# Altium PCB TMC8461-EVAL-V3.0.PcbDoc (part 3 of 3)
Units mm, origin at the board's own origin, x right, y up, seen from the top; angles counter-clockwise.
Board outline 79 x 85 mm, 4 copper layers (Top Layer, Mid1, Mid2, Bottom Layer), stack 1.572 mm thick; 182 components, 192 nets, 883 pads, 381 vias.
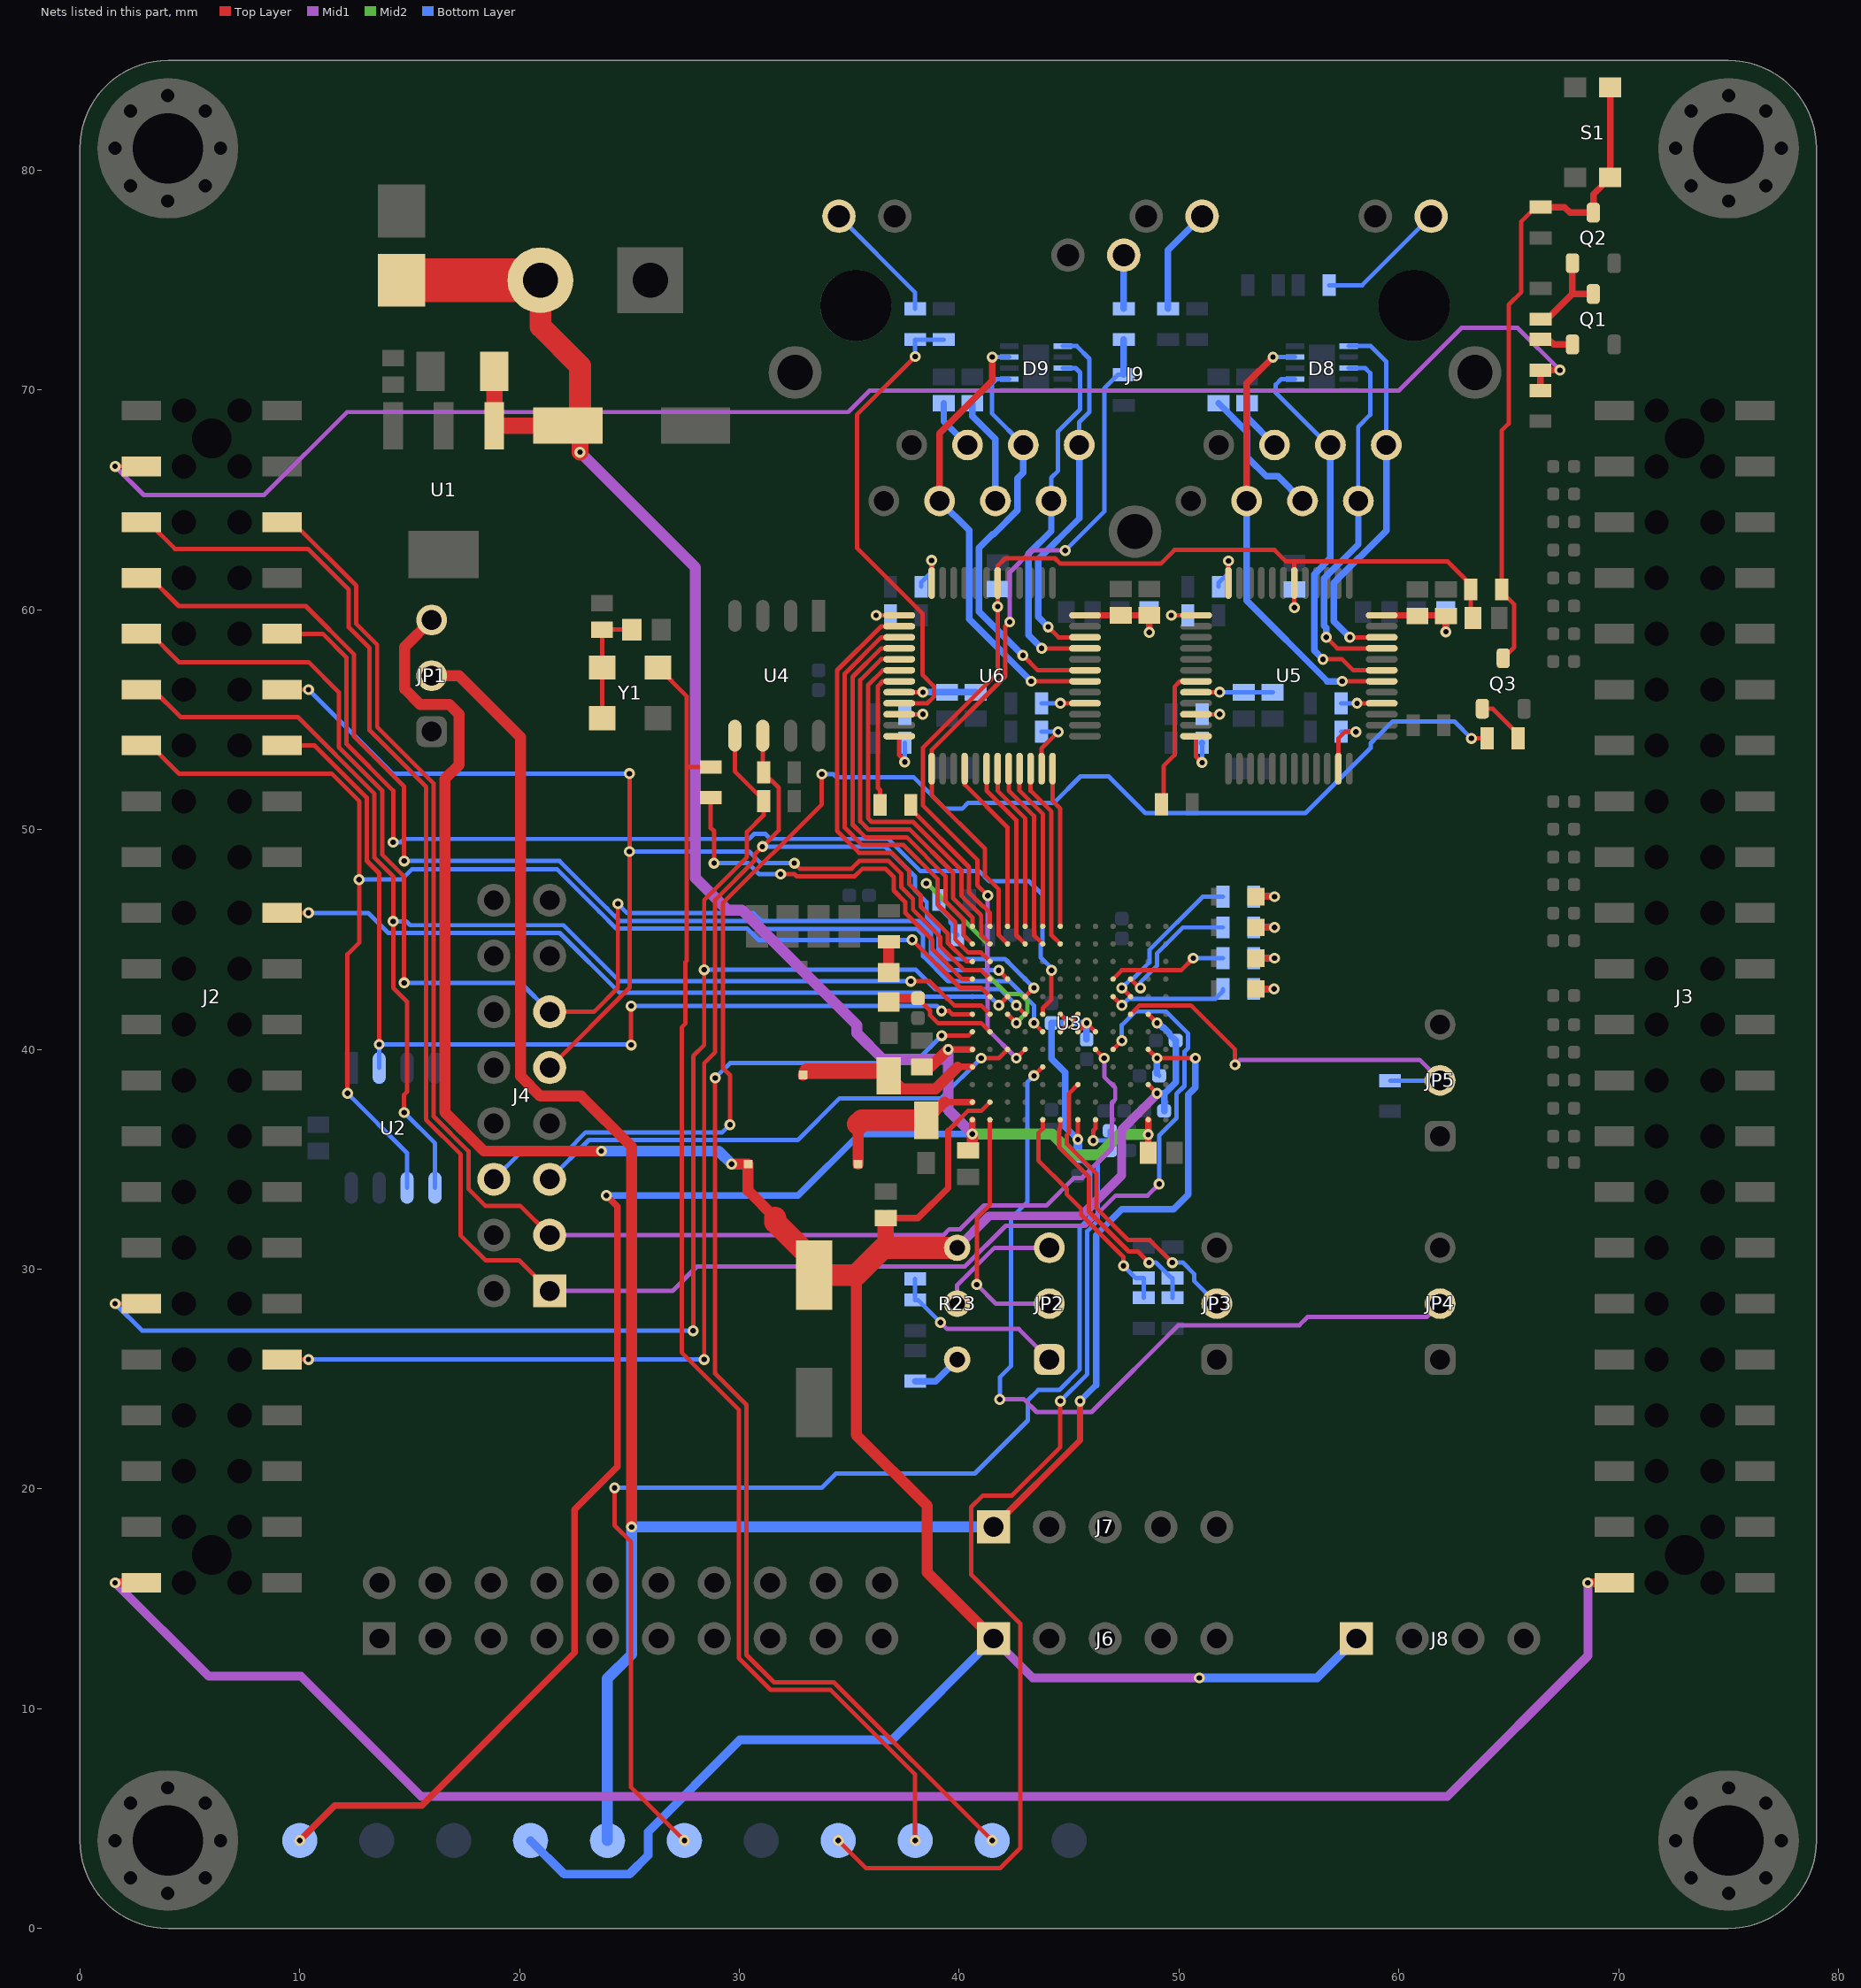
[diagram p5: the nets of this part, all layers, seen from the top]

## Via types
v1: diameter 0.5, hole 0.25, Top Layer to Bottom Layer, tented both sides, 379 vias
v2: diameter 0.5/0.5/0.5/0.5 (per signal layer), hole 0.25, Top Layer to Bottom Layer, tented both sides, 1 vias
v3: diameter 0.55, hole 0.25, Top Layer to Bottom Layer, tented both sides, 1 vias

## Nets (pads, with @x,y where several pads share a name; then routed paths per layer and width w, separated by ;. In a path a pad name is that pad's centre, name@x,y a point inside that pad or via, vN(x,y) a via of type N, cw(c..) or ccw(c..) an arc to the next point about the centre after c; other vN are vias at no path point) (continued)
MII2_LED_ACT: R63.1 R69.1 U6.9 | length 21.8
  Top Layer w0.2: U6.9@37.275,55.75 38.557,55.75 38.85,56.043 38.85,56.525 38.325,57.05 38.325,59.841 35.35,62.816 35.35,68.875 v1(38,71.525)
  Bottom Layer w0.2: v1(38,71.525) R69.1@38,72.3 R63.1@39.3,72.3
MII2_LINK: R66.2 R68.1 U3.K2 U6.13 | length 33.6
  Top Layer w0.2: U3.K2@42.2,44.8 41.8,45.2 41.8,47.275 41.175,47.9 41.175,49.125 38.75,51.55 U6.13@38.75,52.775 38.75,53.625 42.1,56.975 42.1,59.25 v1(42.3,59.45)
  Mid1 w0.2: v1(42.3,59.45) 42.3,61.7 43.3,62.7 v1(44.825,62.7)
  Bottom Layer w0.2: v1(44.825,62.7) 46.6,64.475 46.6,70.075 47.225,70.7 R66.2@47.49,70.7
  Bottom Layer w0.3: R66.2@47.49,70.7 R68.1@47.49,72.3
MII2_RX_CLK: U3.K1 U6.16 | length 8
  Top Layer w0.2: U6.16@40.25,52.775 40.25,52.05 42.2,50.1 U3.K1@42.2,45.6
MII2_RX_DV: U3.G2 U6.22 | length 8.5
  Top Layer w0.2: U6.22@43.25,52.775 43.25,51.767 44.2,50.817 44.2,45.2 U3.G2@44.6,44.8
MII2_RX_ER: U3.G1 U6.24 | length 7.3
  Top Layer w0.2: U6.24@44.25,52.775 44.25,51.305 44.6,50.955 U3.G1@44.6,45.6
MII2_RXD0: U3.H1 U6.21 | length 7.6
  Top Layer w0.2: U6.21@42.75,52.775 42.75,51.772 43.8,50.722 U3.H1@43.8,45.6
MII2_RXD1: U3.H2 U6.20 | length 8.6
  Top Layer w0.2: U6.20@42.25,52.775 42.25,51.777 43.4,50.627 43.4,45.2 U3.H2@43.8,44.8
MII2_RXD2: U3.J1 U6.19 | length 7.7
  Top Layer w0.2: U6.19@41.75,52.775 41.75,51.768 43,50.518 U3.J1@43,45.6
MII2_RXD3: U3.J2 U6.18 | length 8.7
  Top Layer w0.2: U6.18@41.25,52.775 41.25,51.773 42.6,50.423 42.6,45.2 U3.J2@43,44.8
MII2_TX_CLK: R59.1 U3.L1 | length 7.1
  Top Layer w0.2: R59.1@37.65,51.125 R59.1@37.65,51.15 ; R59.1@37.8,51.125 37.8,50.95 40.45,48.3 40.45,47.143 41.093,46.5 41.115,46.5 41.4,46.215 U3.L1@41.4,45.6
MII2_TX_EN: U3.M3 U6.2 | length 20.5
  Top Layer w0.2: U6.2@37.275,59.25 36.447,59.25 34.45,57.253 34.45,49.942 35.442,48.95 36.907,48.95 37.725,48.132 37.725,47.518 38.25,46.993 38.25,46.5 39.483,45.267 39.483,44.847 40.33,44 U3.M3@40.6,44
MII2_TXD0: U3.L2 U6.6 | length 16.9
  Top Layer w0.2: U6.6@37.275,57.25 36.53,57.25 35.85,56.57 35.85,50.521 36.021,50.35 37.905,50.35 40.1,48.155 40.1,46.998 40.948,46.15 40.95,46.15 41,46.1 41,45.2 U3.L2@41.4,44.8
MII2_TXD1: U3.M1 U6.5 | length 16.6
  Top Layer w0.2: U6.5@37.275,57.75 36.446,57.75 35.5,56.804 35.5,50.376 35.876,50 37.76,50 39.725,48.035 39.725,46.878 40.6,46.003 U3.M1@40.6,45.6
MII2_TXD2: U3.M2 U6.4 | length 18.2
  Top Layer w0.2: U6.4@37.275,58.25 36.451,58.25 35.15,56.949 35.15,50.232 35.732,49.65 37.615,49.65 39.375,47.89 39.375,46.733 40.2,45.908 40.2,45.2 U3.M2@40.6,44.8
MII2_TXD3: U3.L3 U6.3 | length 20.4
  Top Layer w0.2: U6.3@37.275,58.75 36.456,58.75 34.8,57.094 34.8,50.087 35.587,49.3 37.47,49.3 39.025,47.745 39.025,46.588 39.833,45.78 39.833,44.992 40.418,44.407 40.993,44.407 U3.L3@41.4,44
NetC13_2: C13.2 L1.2 U3.L7 | length 5.4
  Top Layer w0.2: L1.2@36.8,42.16 L1.2@36.965,42.325 ; C13.2@38.125,42.325 38.125,42.311 38.68,41.756 38.68,41.55 39.03,41.2 41,41.2 U3.L7@41.4,40.8
  Top Layer w0.4: L1.2@36.965,42.325 C13.2@38.125,42.325
NetC16_2: C16.2 C17.2 TP8.1 U3.E12 | length 47.9
  Top Layer w0.2: v1(34.5,4) 35.75,2.75 41.875,2.75 42.775,3.65 42.775,13.875 40.55,16.1 40.55,19.175 41.075,19.7 42.4,19.7 44.6,21.9 v1(44.6,24) ; v1(46.1,35.85) 46.1,36.3 46.2,36.4 U3.E12@46.2,36.8
  Bottom Layer w0.2: v1(44.6,24) 45.825,25.225 45.825,31.725 46.305,32.205 46.305,34.855 C16.2@46.85,35.4 46.85,35.85 ; v1(46.1,35.85) 46.85,35.85 ; C17.2@46.85,36.3 46.85,35.85
NetC28_2: C28.2 L4.1 Y1.1 Y1.4 | length 5.5
  Top Layer w0.2: Y1.1@23.4,55 Y1.1@23.4,55.125 ; Y1.1@23.76,55.075 Y1.4@23.76,57.375 23.76,59.09 C28.2@23.75,59.1 L4.1@25.11,59.1
NetC34_2: C34.2 C35.2 L5.2 U5.36 | length 4.6
  Top Layer w0.3: U5.36@59.225,59.75 62.125,59.75 62.14,59.735 v1(62.14,59)
  Bottom Layer w0.3: v1(62.14,59) L5.2@62.14,59.9
NetC36_2: C36.2 C37.2 U5.8 | length 3.5
  Top Layer w0.2: U5.8@50.775,56.25 v1(51.85,56.25)
  Bottom Layer w0.2: v1(51.85,56.25) C37.2@54.275,56.25
NetC38_2: C38.2 J9.A4 | length 6.3
  Bottom Layer w0.3: C38.2@51.8,69.4 53.1,68.1 53.1,66.95 53.975,66.075 54.505,66.075 J9.A4@55.62,64.96
NetC39_2: C39.2 J9.A5 | length 2.4
  Bottom Layer w0.3: C39.2@53.1,69.4 53.1,68.75 J9.A5@54.35,67.5
NetC43_2: C43.2 C44.2 L6.2 U6.36 | length 4.6
  Top Layer w0.3: U6.36@45.725,59.75 C43.2@48.65,59.75 v1(48.65,58.975)
  Bottom Layer w0.3: L6.2@48.64,59.9 48.64,58.985 v1(48.65,58.975)
NetC45_2: C45.2 C46.2 U6.8 | length 3.5
  Top Layer w0.2: U6.8@37.275,56.25 v1(38.35,56.25)
  Bottom Layer w0.3: v1(38.35,56.25) C46.2@39.45,56.25 C45.2@40.75,56.25
NetC47_2: C47.2 J9.B4 | length 4.9
  Bottom Layer w0.3: C47.2@40.6,69.4 40.6,68.825 41.65,67.775 J9.B4@41.65,64.96
NetC48_2: C48.2 J9.B5 | length 2.3
  Bottom Layer w0.3: C48.2@39.3,69.4 39.3,68.58 J9.B5@40.38,67.5
NetD2_1: D2.1 L2.1 U3.M9 | length 8.5
  Top Layer w0.3: 39.925,39.2 U3.M9@40.6,39.2
  Top Layer w0.5: L2.1@32.899,38.833 L2.1@33.065,39 ; D2.1@36.6,39 D2.1@36.8,38.8 37.4,38.2 38.925,38.2 39.925,39.2
  Top Layer w0.7: L2.1@33.065,39 D2.1@36.6,39
NetD3_1: D3.1 L3.1 U3.M11 | length 7.4
  Top Layer w0.2: D3.1@38.5,36.775 D3.1@38.575,36.85
  Top Layer w0.3: 39.325,37.6 U3.M11@40.6,37.6
  Top Layer w0.5: L3.1@35.399,34.78 35.399,36.599 ; D3.1@38.575,36.85 39.325,37.6
  Top Layer w1: 35.399,36.599 35.575,36.775 D3.1@38.5,36.775
NetD4_2: D4.2 R36.2 | length 1.8
  Top Layer w0.3: D4.2@53.5,46.95 v1(54.35,46.95)
  Bottom Layer w0.3: R36.2@53.4,46.95 v1(54.35,46.95)
NetD5_2: D5.2 R37.2 | length 1.8
  Top Layer w0.3: D5.2@53.5,45.55 v1(54.35,45.55)
  Bottom Layer w0.3: R37.2@53.4,45.55 v1(54.35,45.55)
NetD6_2: D6.2 R38.2 | length 1.8
  Top Layer w0.3: D6.2@53.5,44.15 v1(54.35,44.15)
  Bottom Layer w0.3: R38.2@53.4,44.15 v1(54.35,44.15)
NetD7_2: D7.2 R39.2 | length 1.7
  Top Layer w0.3: D7.2@53.5,42.75 v1(54.325,42.75)
  Bottom Layer w0.3: R39.2@53.4,42.75 v1(54.325,42.75)
NetJ9_A9: J9.A9 R57.2 | length 5.9
  Bottom Layer w0.2: R57.2@56.825,74.775 58.335,74.775 J9.A9@61.47,77.91
NetJ9_A11: J9.A11 R58.2 | length 4.9
  Bottom Layer w0.3: R58.2@49.5,73.7 49.5,76.36 J9.A11@51.05,77.91
NetJ9_B9: J9.B9 R68.2 | length 2.4
  Bottom Layer w0.3: R68.2@47.49,73.7 J9.B9@47.49,76.14
NetJ9_B12: J9.B12 R69.2 | length 5.6
  Bottom Layer w0.2: J9.B12@34.53,77.91 38,74.44 R69.2@38,73.7
NetJP2_1: JP2.1 R25.1 R26.2 | length 8.2
  Mid1 w0.2: v1(39.15,27.575) 39.45,27.275 42.715,27.275 JP2.1@44.1,25.89
  Bottom Layer w0.2: R25.1@38,29.55 R26.2@38,28.6 38.125,28.6 v1(39.15,27.575)
NetJP2_2: JP2.2 U3.L12 | length 11.4
  Top Layer w0.2: v1(40.8,29.3) 40.8,32.325 41.4,32.925 U3.L12@41.4,36.8
  Mid1 w0.2: v1(40.8,29.3) 41.67,28.43 JP2.2@44.1,28.43
NetJP2_3: JP2.3 R23.2 | length 5.7
  Mid1 w0.2: R23.2@39.909,28.43 39.909,29.273 41.606,30.97 JP2.3@44.1,30.97
NetJP3_2: JP3.2 U3.F10 | length 13.9
  Top Layer w0.2: U3.F10@45.4,38.4 45,38 45,36.207 44.9,36.107 44.9,35.693 46.25,34.343 46.25,32.768 47.693,31.325 48.675,31.325 v1(49.7,30.3)
  Bottom Layer w0.2: v1(49.7,30.3) 50.175,30.3 50.7,29.775 50.7,29.45 JP3.2@51.72,28.43
NetJP4_2: JP4.2 U3.H9 | length 38.2
  Top Layer w0.2: v1(43.4,38.8) U3.H9@43.8,39.2
  Mid1 w0.2: v1(41.85,24.075) 42.95,24.075 43.525,23.5 46.025,23.5 49.975,27.45 55.475,27.45 55.85,27.825 61.275,27.825 JP4.2@61.88,28.43
  Bottom Layer w0.2: v1(41.85,24.075) 41.85,25.085 42.35,25.585 42.35,32.3 43.1,33.05 43.1,38.5 v1(43.4,38.8)
NetJP5_2: JP5.2 R47.1 U3.C6 | length 18.7
  Top Layer w0.2: U3.C6@47.8,41.6 48.2,42 50.542,42 52.55,39.992 v1(52.55,39.3) ; v1@52.578,39.252 v1@52.578,39.4
  Mid1 w0.2: v1(52.55,39.3) 52.775,39.525 60.945,39.525 JP5.2@61.88,38.59
  Bottom Layer w0.2: R47.1@59.6,38.58 61.87,38.58 JP5.2@61.88,38.59
NetL1_1: L1.1 R22.2 | length 1.5
  Top Layer w0.5: L1.1@36.8,43.49 R22.2@36.8,44.9 R22.2@36.8,44.95
NetQ1_1: Q1.1 R31.1 | length 1.6
  Top Layer w0.3: R31.1@66.445,72.305 66.81,72.305 67.04,72.075 Q1.1@67.9,72.075
NetQ1_3: Q1.3 Q2.1 R32.1 | length 4.3
  Top Layer w0.3: R32.1@66.45,73.225 66.74,73.225 67.89,74.375 Q1.3@68.85,74.375 ; 67.9,74.385 Q2.1@67.9,75.775
NetQ2_3: Q2.3 Q3.3 R33.1 R34.1 S1.1 S1.2 | length 30.4
  Top Layer w0.2: Q3.3@64.75,57.8 65.25,58.3 65.25,60.25 64.675,60.825 R34.1@64.675,60.925 64.675,68.15 65,68.475 65,73.882 65.575,74.457 65.575,77.675 66.225,78.325 R33.1@66.45,78.325
  Top Layer w0.3: R33.1@66.45,78.325 67.54,78.325 67.79,78.075 Q2.3@68.85,78.075 68.85,78.91 S1.2@69.62,79.68 S1.1@69.62,83.78
NetQ3_1: Q3.1 R35.1 | length 2.6
  Top Layer w0.2: Q3.1@63.8,55.225 Q3.1@63.8,55.5 64.275,55.5 65.425,54.35 R35.1@65.425,54.15
NetR23_1: R23.1 R24.2 | length 2.3
  Bottom Layer w0.3: R24.2@38,24.9 38.919,24.9 R23.1@39.909,25.89 R23.1@39.92,25.901
NetR27_1: R27.1 TP9.1 Y1.3 | length 61.1
  Top Layer w0.2: Y1.3@26.3,57.375 27.6,56.075 27.6,52.85 ; R27.1@28.7,52.85 27.6,52.85 ; v1(38,4) 38,7.005 34.155,10.85 31.43,10.85 29.975,12.305 29.975,23.608 27.375,26.208 27.375,41 27.55,41.175 27.55,43.977 27.6,44.027 27.6,52.85
NetR27_2: R27.2 U3.M4 | length 18.2
  Top Layer w0.2: R27.2@28.7,51.45 28.7,50.075 28.85,49.925 v1(28.85,48.475) ; v1(31.875,47.975) 32.505,47.975 32.605,47.875 35.25,47.875 35.6,48.225 36.642,48.225 37.025,47.842 37.025,47.229 37.55,46.704 37.55,46.21 38.783,44.977 38.783,44.557 40.14,43.2 U3.M4@40.6,43.2
  Bottom Layer w0.2: v1(28.85,48.475) 30.4,48.475 30.9,47.975 v1(31.875,47.975)
NetR28_1: R28.1 R29.2 U3.K6 | length 12.4
  Top Layer w0.2: U3.K6@42.2,41.6 v1(42.6,41.2)
  Mid2 w0.2: v1(38.502,47.552) 38.548,47.552 41.275,44.825 41.275,43.41 42.16,42.525 42.782,42.525 43.1,42.207 43.1,41.7 v1(42.6,41.2)
  Bottom Layer w0.2: v1(38.502,47.552) 38.548,47.552 39.075,47.025 R29.2@39.075,46.8 39.075,46.475 39.6,45.95 39.6,45.775 39.725,45.65 39.725,45.4 R28.1@39.925,45.2
NetR36_1: R36.1 U3.C5 | length 7.4
  Top Layer w0.2: v1@47.5,42.7 v1(47.4,42.8) U3.C5@47.8,42.4
  Bottom Layer w0.2: v1(47.4,42.8) 47.8,43.2 47.897,43.2 48.655,43.958 48.655,44.525 51.08,46.95 R36.1@52,46.95
NetR37_1: R37.1 U3.C4 | length 6
  Top Layer w0.2: U3.C4@47.8,43.2 48.2,42.8 v1(48.25,42.8)
  Bottom Layer w0.2: v1(48.25,42.8) 48.25,43.058 49.005,43.813 49.005,44.38 50.175,45.55 R37.1@52,45.55
NetR38_1: R38.1 U3.D4 | length 5.4
  Top Layer w0.2: U3.D4@47,43.2 47.4,43.6 50.1,43.6 v1(50.65,44.15)
  Bottom Layer w0.2: v1@50.6,44.15 v1(50.65,44.15) R38.1@52,44.15
NetR39_1: R39.1 U3.D5 | length 5.5
  Top Layer w0.2: U3.D5@47,42.4 v1(47.4,42)
  Bottom Layer w0.2: v1(47.4,42) 47.7,42.3 51.65,42.3 52,42.65 R39.1@52,42.75
NetR40_1: R40.1 R42.2 U3.G12 | length 10.7
  Top Layer w0.2: U3.G12@44.6,36.8 44.6,36.4 44.55,36.35 44.55,35.548 45.9,34.198 45.9,32.62 47.712,30.808 48.127,30.808 v1(48.635,30.3)
  Bottom Layer w0.2: v1(48.635,30.3) 48.95,30.3 49.65,29.6 R40.1@49.7,29.6 R42.2@49.7,28.7
NetR41_1: R41.1 R43.2 U3.H12 | length 10.4
  Top Layer w0.2: U3.H12@43.8,36.8 43.8,36.385 43.6,36.185 43.6,34.943 44.9,33.643 44.9,33.393 45.55,32.743 45.55,32.475 47.475,30.55 v1(47.475,30.15)
  Bottom Layer w0.2: v1(47.475,30.15) 48.025,29.6 R41.1@48.4,29.6 R43.2@48.4,28.7
NetR48_2: R48.2 U5.7 | length 6.6
  Top Layer w0.2: R48.2@49.3,51.15 49.3,52.895 49.8,53.395 49.8,56.5 50.05,56.75 U5.7@50.775,56.75
NetR49_2: R49.2 U5.23 | length 3
  Top Layer w0.2: U5.23@57.25,52.775 57.25,54.15 57.55,54.45 v1(58.05,54.45)
  Bottom Layer w0.2: R49.2@57.375,54.45 v1(58.05,54.45)
NetR50_2: R50.2 U5.1 | length 1.9
  Top Layer w0.2: v1(49.65,59.75) U5.1@50.775,59.75
  Bottom Layer w0.2: v1(49.65,59.75) R50.2@50.4,59.75
NetR51_2: R51.2 U5.28 | length 1.8
  Top Layer w0.2: v1(58.1,55.75) U5.28@59.225,55.75
  Bottom Layer w0.2: R51.2@57.375,55.75 v1(58.1,55.75)
NetR53_2: R53.2 U5.10 | length 1.9
  Top Layer w0.2: U5.10@50.775,55.25 v1(51.85,55.25)
  Bottom Layer w0.2: R53.2@51.05,55.25 v1(51.85,55.25)
NetR54_2: R54.2 U5.12 | length 2.4
  Top Layer w0.2: U5.12@50.775,54.25 50.775,53.325 v1(51.05,53.05)
  Bottom Layer w0.2: v1(51.05,53.05) R54.2@51.05,53.95 R54.2@51.05,53.725
NetR56_1: R56.1 U5.48 | length 2.4
  Top Layer w0.2: U5.48@52.25,61.225 v1(52.25,62.225)
  Bottom Layer w0.2: R56.1@51.8,61.05 51.8,61.225 52.25,61.675 v1(52.25,62.225)
NetR59_2: R59.2 U6.7 | length 6.5
  Top Layer w0.2: R59.2@36.4,51.125 36.4,51.8 36.3,51.9 36.3,56.525 36.525,56.75 U6.7@37.275,56.75
NetR60_2: R60.2 U6.23 | length 2.7
  Top Layer w0.2: U6.23@43.75,52.775 43.75,53.7 v1(44.5,54.45)
  Bottom Layer w0.2: R60.2@43.75,54.45 v1(44.5,54.45)
NetR61_2: R61.2 U6.1 | length 1.7
  Top Layer w0.2: v1(36.225,59.75) U6.1@37.275,59.75
  Bottom Layer w0.2: v1(36.225,59.75) R61.2@36.875,59.75
NetR62_2: R62.2 U6.28 | length 2
  Top Layer w0.2: v1(44.6,55.75) U6.28@45.725,55.75
  Bottom Layer w0.2: R62.2@43.75,55.75 v1(44.6,55.75)
NetR64_2: R64.2 U6.10 | length 1.9
  Top Layer w0.2: U6.10@37.275,55.25 v1(38.35,55.25)
  Bottom Layer w0.2: R64.2@37.525,55.25 v1(38.35,55.25)
NetR65_2: R65.2 U6.12 | length 2.2
  Top Layer w0.2: U6.12@37.275,54.25 37.275,53.386 37.525,53.136 v1(37.525,53.075)
  Bottom Layer w0.2: v1(37.525,53.075) R65.2@37.525,53.95
NetR67_1: R67.1 U6.48 | length 2.4
  Top Layer w0.2: U6.48@38.75,61.225 v1(38.75,62.25)
  Bottom Layer w0.2: R67.1@38.275,61.05 38.275,61.25 38.75,61.725 v1(38.75,62.25)
NetTP10_1: TP10.1 U3.M7 | length 54.1
  Top Layer w0.2: v1(28.9,38.7) 28.9,25.25 30.325,23.825 30.325,12.45 31.575,11.2 34.3,11.2 v1(41.5,4) ; v1(39.202,40.623) 40.423,40.623 U3.M7@40.6,40.8
  Bottom Layer w0.2: v1(28.9,38.7) 29.575,39.375 37.954,39.375 v1(39.202,40.623)
PDI_EOF: J2.35 J4.11 U3.K4 | length 58.8
  Top Layer w0.2: J2.35@2.8,58.91 3.215,58.91 4.5,57.625 10.4,57.625 11.775,56.25 11.775,53.755 13.75,51.78 13.75,48.868 14.75,47.868 v1(14.75,43.025) ; J4.11@21.37,41.71 23.385,41.71 24.475,42.8 v1(24.475,46.625) ; v1(41.8,43.6) U3.K4@42.2,43.2
  Bottom Layer w0.2: v1(14.75,43.025) 20.055,43.025 J4.11@21.37,41.71 ; v1(24.475,46.625) 24.9,46.2 26.175,46.2 30.64,46.2 31.005,45.835 38.212,45.835 38.71,45.337 38.71,44.385 39.495,43.6 v1(41.8,43.6)
PDI_SOF: J2.34 J4.9 U3.L4 | length 52.3
  Top Layer w0.2: J2.34@9.2,56.37 v1(10.4,56.37) ; J4.9@21.37,39.17 25,42.8 v1(25,49) v1(25,52.55) ; v1(32.5,48.475) 32.75,48.225 35.105,48.225 35.455,48.575 36.787,48.575 37.375,47.987 37.375,47.374 37.9,46.849 37.9,46.355 39.133,45.122 39.133,44.702 40.235,43.6 41,43.6 U3.L4@41.4,43.2
  Bottom Layer w0.2: v1(10.4,56.37) 14.22,52.55 v1(25,52.55) ; v1(25,49) 30.45,49 30.975,48.475 v1(32.5,48.475)
PDI_SPI_IRQ: J2.26 U3.K5 | length 34.9
  Top Layer w0.2: J2.26@9.2,46.21 v1(10.4,46.21) ; v1(41.8,42) U3.K5@42.2,42.4
  Bottom Layer w0.2: v1(10.4,46.21) 13.115,46.21 14.025,45.3 21.825,45.3 24.55,42.575 38.225,42.575 38.4,42.4 41.4,42.4 v1(41.8,42)
PDI_WD_STATE: J2.37 U3.H7 | length 54.8
  Top Layer w0.2: J2.37@2.8,61.45 3.225,61.45 4.5,60.175 10.275,60.175 12.475,57.975 12.475,54.233 14.75,51.958 v1(14.75,48.575) ; v1(43.4,41.2) U3.H7@43.8,40.8
  Bottom Layer w0.2: v1(14.75,48.575) 21.82,48.575 23.975,46.42 23.975,46.418 24.543,45.85 29.125,45.85 30.495,45.85 30.86,45.485 38.067,45.485 38.36,45.192 38.36,44.24 39.5,43.1 42.3,43.1 43.4,42 v1(43.4,41.2)
PDI_WD_TRIGGER: J2.36 U3.H6 | length 49.3
  Top Layer w0.2: J2.36@9.2,58.91 11.045,58.91 12.125,57.83 12.125,53.9 14.25,51.775 v1(14.25,49.425) ; U3.H6@43.8,41.6 43.8,41.875 43.95,42.025 43.955,42.025 44.2,42.27 v1(44.2,43.6)
  Bottom Layer w0.2: v1(14.25,49.425) 14.6,49.425 14.75,49.575 30.44,49.575 30.665,49.8 31.185,49.8 31.41,49.575 36.775,49.575 38.225,48.125 40.9,48.125 41.375,47.65 43.175,47.65 43.79,47.035 43.79,44.879 43.7,44.789 43.7,44.193 44.2,43.693 v1(44.2,43.6)
PROM_CLK: J2.10 R45.1 U3.J5 U4.6 | length 66.2
  Top Layer w0.2: J2.10@9.2,25.89 v1(10.4,25.89) ; v1(28.4,25.89) 28.4,39.375 28.9,39.875 28.9,46.8 30.7,48.6 30.7,48.875 v1(31.05,49.225) 31.8,49.975 31.8,51.9 R45.1@31.1,52.6 31.065,52.635 U4.6@31.065,54.275 ; U3.J5@43,42.4 v1(43.4,42.8)
  Bottom Layer w0.2: v1(10.4,25.89) v1(28.4,25.89) ; v1(31.05,49.225) 36.63,49.225 38,47.855 38,47.225 38.525,46.7 38.525,46.017 39.06,45.482 39.06,44.53 39.477,44.113 42.088,44.113 v1(43.4,42.8)
PROM_DATA: J2.11 R46.1 U3.J6 U4.5 | length 72.4
  Top Layer w0.2: v1(1.6,28.43) J2.11@2.8,28.43 ; v1(27.9,27.2) 27.9,39.7 28.4,40.2 v1(28.4,43.625) 28.4,46.795 30.35,48.745 30.35,49.9 31.1,50.65 R46.1@31.1,51.3 31.1,51.35 29.795,52.655 U4.5@29.795,54.275 ; v1(42.6,42) U3.J6@43,41.6
  Bottom Layer w0.2: v1(1.6,28.43) 2.83,27.2 v1(27.9,27.2) ; v1@28.35,43.625 v1(28.4,43.625) 38.025,43.625 38.9,42.75 41.85,42.75 v1(42.6,42)
R\E\S\E\T\: C29.2 C33.2 C42.2 R34.2 U3.J8 U5.42 U6.42 | length 54.1
  Top Layer w0.2: v1(41.3,47) 40.825,47.475 40.825,48.625 38.35,51.1 38.35,52.009 38.35,53.725 41.75,57.125 v1(41.75,60.15) U6.42@41.75,61.225 41.75,62 42.1,62.35 44.35,62.35 44.6,62.1 49.168,62.1 49.793,62.725 54.35,62.725 54.875,62.2 55.25,62.2 ; v1(42.6,39.6) U3.J8@43,40 ; v1(55.25,60.1) U5.42@55.25,61.225 55.25,62.2 ; C29.2@63.375,59.625 63.275,59.725 63.275,61.15 62.225,62.2 55.25,62.2
  Mid1 w0.2: v1(41.3,47) 41.3,40.9 v1(42.6,39.6)
  Bottom Layer w0.2: v1(41.75,60.15) C42.2@41.75,60.95 ; v1(55.25,60.1) C33.2@55.25,60.925
R\S\T\_\E\X\T\: J2.41 R30.2 R31.2 | length 73.2
  Top Layer w0.2: v1(1.6,66.53) J2.41@2.8,66.53
  Top Layer w0.3: R30.2@66.445,69.98 R31.2@66.445,70.905 v1(67.325,70.905)
  Mid1 w0.2: v1(1.6,66.53) 2.905,65.225 8.375,65.225 12.15,69 34.95,69 35.925,69.975 60,69.975 62.85,72.825 65.405,72.825 v1(67.325,70.905)
RD_A_N: D8.9 J9.A6 U5.30 | length 20.3
  Top Layer w0.2: v1(57.425,56.75) U5.30@59.225,56.75
  Top Layer w0.3: J9.A6@53.08,64.96 53.08,70.305 v1(54.275,71.5)
  Bottom Layer w0.2: J9.A6@53.08,64.96 J9.A6@53.154,64.96 ; v1(54.275,71.5) D8.9@55.28,71.5
  Bottom Layer w0.3: J9.A6@53.08,64.96 53.08,60.42 56.75,56.75 v1(57.425,56.75)
RD_A_P: D8.7 J9.A3 U5.31 | length 18
  Top Layer w0.2: v1(56.55,57.75) 57.425,57.75 57.925,57.25 U5.31@59.225,57.25
  Bottom Layer w0.2: D8.7@55.28,70.5 54.65,70.5 54.4,70.25 54.4,69.875 56.775,67.5 J9.A3@56.89,67.5
  Bottom Layer w0.3: v1@56.6,57.7 v1(56.55,57.75) 56.15,58.15 56.15,61.6 56.15,61.611 56.89,62.351 J9.A3@56.89,67.5
RD_B_N: D9.9 J9.B6 U6.30 | length 20.7
  Top Layer w0.2: v1(43.275,56.75) U6.30@45.725,56.75
  Top Layer w0.3: J9.B6@39.11,64.96 39.11,68.035 41.5,70.425 v1(41.5,71.5)
  Bottom Layer w0.2: v1(41.5,71.5) D9.9@42.28,71.5
  Bottom Layer w0.3: J9.B6@39.11,64.96 40.45,63.62 40.45,59.575 v1(43.275,56.75)
RD_B_P: D9.7 J9.B3 U6.31 | length 18.6
  Top Layer w0.2: v1(42.9,57.925) 43.575,57.25 U6.31@45.725,57.25
  Bottom Layer w0.2: D9.7@42.28,70.5 41.7,70.5 41.5,70.3 41.5,68.92 J9.B3@42.92,67.5
  Bottom Layer w0.3: v1(42.9,57.925) 40.9,59.925 40.9,62.828 41.522,63.45 41.575,63.45 42.65,64.525 42.65,65.98 42.92,66.25 J9.B3@42.92,67.5
RESET_OUT: J4.5 U3.K8 | length 23.3
  Top Layer w0.2: v1(41,39.6) 41.8,39.6 U3.K8@42.2,40
  Bottom Layer w0.2: J4.5@21.37,34.09 23.155,35.875 32.665,35.875 34.565,37.775 39.175,37.775 v1(41,39.6)
RST_IN: J4.6 R35.2 | length 64.1
  Top Layer w0.2: v1(29.575,36.575) 29.575,38.825 29.25,39.15 29.25,46.65 33.75,51.15 v1(33.75,52.525) ; v1(63.3,54.15) R35.2@64.025,54.15
  Bottom Layer w0.2: J4.6@18.83,34.09 20.09,35.35 22.135,35.35 23.01,36.225 29.225,36.225 v1(29.575,36.575) ; v1(33.75,52.525) 34.275,52.525 34.425,52.375 37.94,52.375 39.365,50.95 40.132,50.95 40.407,51.225 44.318,51.225 45.518,52.425 46.8,52.425 48.475,50.75 55.755,50.75 58.725,53.72 58.725,53.932 59.018,54.225 59.025,54.225 59.725,54.925 62.525,54.925 v1(63.3,54.15)
SPI1_SCK: J2.31 U2.6 U3.L5 | length 61.2
  Top Layer w0.2: J2.31@2.8,53.83 3.22,53.83 4.5,52.55 11.455,52.55 12.7,51.305 v1(12.7,47.725) 12.7,44.85 12.175,44.325 v1(12.175,38) ; v1(37.86,44.985) 40.045,42.8 41,42.8 U3.L5@41.4,42.4
  Bottom Layer w0.2: v1(12.175,38) 14.885,35.29 U2.6@14.885,33.7 ; v1@12.65,47.725 v1(12.7,47.725) 14.638,47.725 15.113,48.2 21.7,48.2 23.625,46.275 23.625,46.273 24.398,45.5 30.35,45.5 30.865,44.985 v1(37.86,44.985)
SPI1_SDI: J2.32 U2.2 U3.M6 | length 46.3
  Top Layer w0.2: J2.32@9.2,53.83 10.67,53.83 13.05,51.45 13.05,48.578 13.615,48.013 v1(13.615,40.225) ; v1@25.075,40.225 v1(25.075,41.975) ; v1(39.2,41.75) 39.533,41.75 39.683,41.6 U3.M6@40.6,41.6
  Bottom Layer w0.2: U2.2@13.615,39.15 v1(13.615,40.225) v1@25.075,40.225 ; v1(25.075,41.975) 38.975,41.975 v1(39.2,41.75)
  other v1: 25.075,40.2
SPI1_SDO: J2.33 U2.5 U3.L6 | length 60.6
  Top Layer w0.2: J2.33@2.8,56.37 3.33,56.37 4.575,55.125 9.91,55.125 13.4,51.635 13.4,48.723 14.25,47.873 v1(14.25,45.825) 14.25,42.8 14.875,42.175 14.875,38.063 14.75,37.938 v1(14.75,37.125) ; v1(37.8,43.1) 38.655,43.1 39.449,42.307 39.471,42.307 39.778,42 41,42 U3.L6@41.4,41.6
  Bottom Layer w0.2: v1(14.25,45.825) 14.85,45.825 15.025,45.65 22,45.65 24.55,43.1 v1(37.8,43.1) ; v1(14.75,37.125) 16.155,35.72 U2.5@16.155,33.7
SYNC_OUT0: J2.39 J4.1 U3.D8 | length 89.4
  Top Layer w0.2: J2.39@2.8,63.99 3.11,63.99 4.325,62.775 10.375,62.775 12.225,60.925 12.225,59.215 13.175,58.265 13.175,54.523 15.75,51.948 15.75,36.798 17.325,35.223 17.325,31.525 18.45,30.4 19.98,30.4 J4.1@21.37,29.01 ; U3.D8@47,40 v1(47.4,40.4)
  Mid1 w0.2: J4.1@21.37,29.01 26.96,29.01 28.07,30.12 40.261,30.12 42.116,31.975 45.75,31.975 47.125,33.35 48.575,33.35 v1(49.1,33.875)
  Bottom Layer w0.2: v1(47.4,40.4) 47.4,41.107 48.018,41.725 49.411,41.725 50.415,40.721 50.415,40.065 50.25,39.9 50.25,38.334 49.89,37.975 49.89,36.879 49.1,36.089 v1(49.1,33.875)
SYNC_OUT1: J2.40 J4.3 U3.E8 | length 70.9
  Top Layer w0.2: J2.40@9.2,63.99 9.685,63.99 12.575,61.1 12.575,59.36 13.525,58.41 13.525,54.668 16.1,52.093 16.1,36.943 17.675,35.368 17.675,33.65 18.45,32.875 20.045,32.875 J4.3@21.37,31.55 ; U3.E8@46.2,40 v1(46.6,39.6)
  Mid1 w0.2: J4.3@21.37,31.55 39.287,31.55 39.557,31.82 40.045,31.82 41.125,32.9 43.975,32.9 45.225,34.15 45.602,34.15 46.95,35.498 46.95,37.575 47.1,37.725 47.1,38.25 46.6,38.75 v1(46.6,39.6)
TD_A_N: D8.3 J9.A2 U5.33 | length 16.7
  Top Layer w0.2: v1(56.7,58.75) 57.2,58.25 U5.33@59.225,58.25
  Bottom Layer w0.2: D8.3@57.72,71 58.475,71 58.7,70.775 58.7,68.875 58.15,68.325 58.15,64.97 J9.A2@58.16,64.96
  Bottom Layer w0.3: v1(56.7,58.75) 56.7,59.175 56.6,59.275 56.6,61.425 58.16,62.985 J9.A2@58.16,64.96
TD_A_P: D8.1 J9.A1 U5.34 | length 17.3
  Top Layer w0.2: v1(57.775,58.75) U5.34@59.225,58.75
  Bottom Layer w0.2: D8.1@57.72,72 58.725,72 59.43,71.295 J9.A1@59.43,67.5
  Bottom Layer w0.3: v1(57.775,58.75) 57.05,59.475 57.05,61.225 59.43,63.605 J9.A1@59.43,67.5
TD_B_N: D9.3 J9.B2 U6.33 | length 16.6
  Top Layer w0.2: v1(43.75,58.25) U6.33@45.725,58.25
  Bottom Layer w0.2: J9.B2@44.19,64.96 44.19,66.015 44.5,66.325 44.5,68.125 45.5,69.125 45.5,70.8 45.3,71 D9.3@44.72,71
  Bottom Layer w0.3: v1(43.75,58.25) 43.15,58.85 43.15,62.55 44.19,63.59 J9.B2@44.19,64.96
TD_B_P: D9.1 J9.B1 U6.34 | length 16.7
  Top Layer w0.2: v1(44.05,59.222) 44.522,58.75 U6.34@45.725,58.75
  Bottom Layer w0.2: D9.1@44.72,72 45.35,72 45.925,71.425 45.925,69 45.46,68.535 J9.B1@45.46,67.5
  Bottom Layer w0.3: v1(44.05,59.222) 43.6,59.672 43.6,62.3 45.46,64.16 J9.B1@45.46,67.5
VDD1V8: C18.2 C22.2 C23.2 TP6.1 U3.E7 U3.F6 U3.F7 U3.F12 U3.G6 U3.G7 | length 64
  Top Layer w0.2: v1(24.325,20.05) 24.325,18.338 25.075,17.588 25.075,6.425 v1(27.5,4) ; U3.G7@44.6,40.8 v1(45,41.2) ; U3.G6@44.6,41.6 v1(45,41.2) ; v1(45.4,35.9) U3.F12@45.4,36.8 ; U3.F7@45.4,40.8 v1(45.8,41.2) U3.E7@46.2,40.8 ; U3.F6@45.4,41.6 v1(45,41.2)
  Bottom Layer w0.2: v1@24.375,20.05 33.742,20.05 34.392,20.7 40.707,20.7 43.125,23.118 43.125,24.032 43.593,24.5 44.55,24.5 45.475,25.425 45.475,31.875 45.955,32.355 45.955,34.595 C18.2@45.4,35.15
  Bottom Layer w0.3: v1(45.4,35.9) 44.825,36.475 44.825,38.953 44.428,39.35 44.425,39.35 44.2,39.575 C23.2@44.2,41.2 v1(45,41.2) v1(45.8,41.2) C22.2@45.8,40.45
  Bottom Layer w0.4: C18.2@45.4,35.15 v1(45.4,35.9)
VIO2: C21.2 J7.1 JP1.2 TP5.1 U3.B8 | length 105.2
  Top Layer w0.2: U3.B8@48.6,40 v1(49,39.6) v1(50.75,39.6)
  Top Layer w0.3: J7.1@41.56,18.27 45.5,22.21 v1(45.5,24)
  Top Layer w0.5: JP1.2@16,57 17.25,57 20.05,54.2 20.05,38.775 20.95,37.875 22.8,37.875 25.1,35.575 v1(25.1,18.27)
  Bottom Layer w0.2: C21.2@49,38.9 C21.2@49.1,38.8
  Bottom Layer w0.3: v1(45.5,24) 46.225,24.725 46.225,31.55 47.4,32.725 49.75,32.725 50.425,33.4 50.425,37.944 50.75,38.269 v1(50.75,39.6) ; C21.2@49,38.9 v1(49,39.6)
  Bottom Layer w0.5: TP5.1@24,4 24,11.375 25.1,12.475 v1(25.1,18.27) J7.1@41.56,18.27
VM: J2.1 J3.1 | length 79.4
  Top Layer w0.4: v1(1.6,15.73) J2.1@2.8,15.73 ; v1(68.6,15.73) J3.1@69.8,15.73
  Mid1 w0.4: v1(1.6,15.73) 5.855,11.475 10.059,11.475 15.534,6 62.2,6 68.6,12.4 v1(68.6,15.73)
VOUT: C14.2 C15.1 C19.2 C20.2 J6.1 J8.1 JP1.3 L3.2 R23.3 R25.2 TP4.1 U3.B6 U3.B10 U3.L11 | length 148
  Top Layer w0.2: 39.5,36.3 40.4,37.2 41,37.2 U3.L11@41.4,37.6 ; U3.B10@48.6,38.4 v1(49,38) ; U3.B6@48.6,41.6 v1(49,41.2)
  Top Layer w0.3: C14.2@36.658,32.326 38.126,32.326 39.5,33.7 39.5,36.3
  Top Layer w0.5: JP1.3@16,59.54 14.775,58.315 14.775,56.4 15.475,55.7 16.8,55.7 17.25,55.25 17.25,52.95 16.6,52.3 16.6,37.15 18.375,35.375 v1(23.725,35.375) ; v1(29.65,34.78) L3.2@30.399,34.78 30.399,33.572 31.629,32.342 ; 35.316,29.73 35.316,22.459 38.55,19.225 38.55,16.2 J6.1@41.56,13.19
  Top Layer w0.75: 36.658,30.995 C14.2@36.658,32.326
  Top Layer w1: 31.629,32.342 31.629,32.138 33.407,30.36 C15.1@33.407,29.73 35.316,29.73 36.556,30.97 36.683,30.97 ; 36.658,30.995 36.683,30.97 ; R23.3@39.909,30.97 36.683,30.97
  Mid1 w0.4: R23.3@39.909,30.97 41.364,32.425 45.55,32.425 47.4,34.275 47.4,36.351 49,37.951 v1(49,38) ; J6.1@41.56,13.19 43.35,11.4 v1(50.925,11.4)
  Bottom Layer w0.2: v1(49,41.2) v1@49.05,41.2 ; 49.325,38 49.35,38
  Bottom Layer w0.3: R25.2@38,30.95 R23.3@39.889,30.95 ; v1(49,38) 49.325,38 C19.2@49.325,37.2 ; v1@49.05,41.2 49.245,41.005 49.302,41.005 49.565,40.742 49.565,40.685 C20.2@49.85,40.4 49.85,38.5 49.35,38
  Bottom Layer w0.4: TP4.1@20.5,4 22.025,2.475 25,2.475 25.85,3.325 25.85,4.4 30.025,8.575 36.945,8.575 J6.1@41.56,13.19 ; v1(50.925,11.4) 56.28,11.4 J8.1@58.07,13.19
  Bottom Layer w0.5: v1(23.725,35.375) 29.055,35.375 v1(29.65,34.78) ; R23.3@39.889,30.95 R23.3@39.909,30.97
VS: C1.1 C2.2 C5.2 C6.2 C7.2 D1.1 J1.2 TP1.1 U1.1 U3.B12 U3.M8 U3.M12 | length 131.8
  Top Layer w0.3: v1(10,4) 11.6,5.6 15.55,5.6 22.5,12.55 22.5,19.067 24.45,21.017 24.45,32.85 v1(23.95,33.35) ; v1(39.5,40) U3.M8@40.6,40 ; C7.2@40.4,35.4 C7.2@40.6,35.6 ; v1(40.6,36.15) U3.M12@40.6,36.8 ; C5.2@48.6,35.4 v1(48.6,36.125) U3.B12@48.6,36.8
  Top Layer w0.5: U1.1@18.85,68.375 U1.1@18.855,68.38 ; C6.2@38.3,39.2 38.7,39.2 v1(39.5,40) ; C7.2@40.6,35.6 v1(40.6,36.15)
  Top Layer w0.75: C2.2@18.9,70.85 18.855,70.805 18.855,68.38 C1.1@22.205,68.38 ; v1(22.75,67.175) 22.755,67.18 C1.1@22.755,68.38
  Top Layer w1: D1.1@14.475,75 D1.1@14.625,75 ; J1.2@20.95,75 20.95,72.9 22.755,71.095 C1.1@22.755,68.38
  Top Layer w2: D1.1@14.625,75 J1.2@20.95,75
  Mid1 w0.5: v1(22.75,67.175) 28,61.925 28,47.8 29.463,46.337 30.113,46.337 35.35,41.1 35.35,40.731 36.531,39.55 39.5,39.55 ; v1(39.5,40) 39.5,39.55 ; v1(40.6,36.15) 39.5,37.25 39.5,39.55
  Mid2 w0.5: v1(40.6,36.15) 44.231,36.15 45.181,35.2 46.369,35.2 47.294,36.125 v1(48.6,36.125)
  Bottom Layer w0.3: v1(23.95,33.35) 32.675,33.35 35.475,36.15 v1(40.6,36.15)
pads on no net: D8.2 D8.4 D8.5 D8.6 D8.8 D8.10 D9.2 D9.4 D9.5 D9.6 D9.8 D9.10 J2.0 J2.17 J2.18 J2.20 J2.21 J2.22 J3.0 J3.5 J3.6 J3.10 J3.11 J9. J9.A7 J9.B7 U3.A4 U3.B5 U3.H5 U3.L8 U5.15 U5.27 U5.32 U5.37 U5.38 U5.39 U5.40 U5.41 U5.43 U5.44 U5.47 U6.15 U6.27 U6.32 U6.37 U6.38 U6.39 U6.40 U6.41 U6.43 U6.44 U6.47

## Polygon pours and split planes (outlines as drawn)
GND on Bottom Layer "GND-bot-last" (solid, remove dead copper, pour order 290): 0.075,0 0.075,85 79.05,85 79.05,0
GND on Mid2 "GND-mid2" (solid, remove dead copper, pour order 276): 79,85.2 79,0.2 0,0.2 0,85.2
+3V3 on Mid1 "+3V3 on Mid1" (solid, remove dead copper, pour order 268): 62.375,53.425 60.95,52 58.4,52 48.5,42.1 48.5,36 40.525,36 28.5,48.025 28.5,61.5 62.375,61.5
GND on Mid1 "GND-MID1" (solid, remove dead copper, pour order 292): -0.025,0.1 -0.025,85.1 78.975,85.1 78.975,0.1
GND on Top Layer "GND-top-last" (solid, remove dead copper, pour order 261): -0.025,0.1 -0.025,85.1 78.975,85.1 78.975,0.1
no net on Top Overlay "Triip" (solid): 71.375,5.1 71.375,2.9 44.55,2.9 44.55,5.1
no net on Top Overlay "Triip" (solid): 7.625,2.9 7.625,5.1 33.45,5.1 33.45,2.9
no net on Bottom Overlay "Triip" (solid): 43.908,17.119 ccw(c43.8,17.187) 43.869,17.295 cw(c73.052,63.328) 38.972,20.793 ccw(c4.265,-21.562) 16.768,31.75 ccw(c16.739,31.626) 16.739,31.753 11.186,32.736 ccw(c11.164,32.613) 11.179,32.737 ccw(c11.15,32.615) 11.025,32.615 11.025,20.218 ccw(c11.15,20.218) 11.034,20.172 ccw(c11.153,20.134) 11.028,20.134 ccw(c14.153,20.134) 14.153,17.009 ccw(c14.153,17.134) 14.153,17.009 43.789,17.035 ccw(c43.789,17.16)

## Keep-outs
Keep-Out Layer:
  lines w0.5: 0,4 ccw(c4,4) 4,0 ; 0,81 cw(c4,81) 4,85 ; 75,0 ccw(c75,4) 79,4 ; 75,85 cw(c75,81) 79,81 ; 0,0 79,0 79,85 0,85 0,0

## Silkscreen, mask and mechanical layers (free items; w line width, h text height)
Top Overlay:
  drawing of 870 lines, arcs and shapes, not listed
  text "5-35V" at 11,81.45 h1.2
  text "+" at 20.125,70.425 h4
  text "LINK OUT" at 31.025,63.225 h1 r90
  text "LINK IN" at 65.25,62.75 h1 r90
  text "SII PROM" at 28.05,61 h1
  text "VOUT" at 17.6,59.025 h1
  text "VIO2" at 17.625,56.525 h1
  text "5V" at 17.675,53.95 h1
  text "100MHz" at 22.15,52.625 h1
  text "RefCLK" at 22.175,51.175 h1
  text "PHY 1" at 39.175,50.7 h1
  text "PHY 0" at 52.65,50.65 h1
  text "RUN" at 54.175,46.5 h1
  text "GND" at 14.525,46.325 h1
  text "GND" at 22.95,46.3 h1
  text "ERROR" at 54.175,45.075 h1
  text "CLK 16M" at 22.975,43.775 h1
  text "+5V REG" at 10.55,43.675 h1
  text "A" at 55.625,43.65 h1
  text "IN" at 56.925,43.65 h1
  text "A" at 55.6,42.25 h1
  text "OUT" at 56.925,42.225 h1
  text "+3.3V" at 12.675,41.25 h1
  text "PDI EOF" at 22.975,41.25 h1
  text "EXT" at 63.556,40.627 h1
  text "nES" at 63.625,38.925 h1
  text "GND" at 14.525,38.75 h1
  text "PDI SOF" at 22.975,38.725 h1
  text "SEL" at 63.575,37.45 h1
  text "MFC ES" at 11.55,36.625 h1
  text "+3.3V" at 22.95,36.125 h1
  text "MCU" at 63.525,35.2 h1
  text "HEADER" at 11.525,34.875 h1
  text "RESET" at 23.125,34.225 h1
  text "RST IN" at 11.5,33.375 h1
  text "OUT" at 23.9,32.775 h1
  text "IN1" at 14.75,31.1 h1
  text "OUT1" at 23.075,30.975 h1
  text "1" at 63.695,30.69 h1
  text "1" at 53.495,30.54 h1
  text "VAR" at 45.875,30.475 h1
  text "PDI" at 53.47,28.665 h1
  text "SH" at 56.5,28.6 h1
  text "PDI" at 63.6,28.575 h1
  text "OUT0" at 22.975,28.45 h1
  text "SYNC" at 28.275,28.425 h1 r90
  text "IN0" at 14.6,28.4 h1
  text "LATCH" at 14,27.95 h1 r90
  text "VOUT" at 45.845,27.965 h1
  text "BUS" at 53.445,27.165 h1
  text "EMU" at 63.55,27.15 h1
  text "0" at 63.72,25.265 h1
  text "Fixed" at 45.65,25.25 h1
  text "0" at 53.545,25.14 h1.2
  text "HV5" at 49.675,20.025 h1 r90
  text "GND" at 52.185,20.05 h1 r90
  text "HV3" at 44.55,19.975 h1 r90
  text "HV4" at 47.1,19.975 h1 r90
  text "VIO2" at 42.025,19.825 h1 r90
  text "IO0" at 16.625,17.51 h1 r90
  text "IO1" at 19.165,17.51 h1 r90
  text "IO2" at 21.705,17.51 h1 r90
  text "IO3" at 24.245,17.51 h1 r90
  text "IO4" at 26.785,17.51 h1 r90
  text "IO5" at 29.325,17.51 h1 r90
  text "IO6" at 31.865,17.51 h1 r90
  text "IO7" at 34.405,17.51 h1 r90
  text "+3.3V" at 36.925,17.4 h1 r90
  text "+3.3V" at 14.125,17.35 h1 r90
  text "VOUT" at 58.535,14.97 h1 r90
  text "HV6" at 61.075,14.97 h1 r90
  text "HV7" at 63.615,14.97 h1 r90
  text "GND" at 66.155,14.97 h1 r90
  text "MFC" at 9.325,10.175 h1
  text "IO9" at 19.225,8.975 h1 r90
  text "IO8" at 16.675,8.925 h1 r90
  text "HV1" at 47.075,8.9 h1 r90
  text "GND" at 14.225,8.825 h1 r90
  text "GND" at 36.95,8.825 h1 r90
  text "GND" at 52.275,8.725 h1 r90
  text "HV0" at 44.6,8.7 h1 r90
  text "HV2" at 49.725,8.575 h1 r90
  text "IO11" at 24.175,8.425 h1 r90
  text "IO10" at 21.65,8.2 h1 r90
  text "IO14" at 31.9,8.15 h1 r90
  text "IO12" at 26.8,8.125 h1 r90
  text "IO13" at 29.375,8.05 h1 r90
  text "IO15" at 34.425,8.05 h1 r90
  text "VOUT" at 42,7.875 h1 r90
  text "TMC8461-EVAL V3.0" at 10.7,0.95 h1.2
Bottom Overlay:
  drawing of 2091 lines, arcs and shapes, not listed
  text "TMC8461-EVAL V3.0" at 34.25,54.325 h1
  text "TMC-Evaluation-Platform" at 35.425,52 h1
  text "Board Supply: / 5V to 35V" at 34.675,45.3 h1
  text "Interfaces: / * SPI Master /   / Slave / * Incremental /   Encoder / * 24 Multifunc- /   tion I/Os" at 38.175,32.525 h1
  text "www.trinamic.com" at 64.75,21.875 h1
  text "+5V / REG" at 12,5.5 h1 r270
  text "VDD5 / OUT" at 32.9,5.425 h1 r270
PCB Outline:
  the board outline again, w0.05
Bottom Courtyard:
  circle w0.05: c36.57,64.96 r1.25
  circle w0.05: c37.84,67.5 r1.25
  circle w0.05: c39.11,64.96 r1.25
  circle w0.05: c40.38,67.5 r1.25
  circle w0.05: c41.65,64.96 r1.25
  circle w0.05: c42.92,67.5 r1.25
  circle w0.05: c44.19,64.96 r1.25
  circle w0.05: c45.46,67.5 r1.25
  circle w0.05: c50.54,64.96 r1.25
  circle w0.05: c51.81,67.5 r1.25
  circle w0.05: c53.08,64.96 r1.25
  circle w0.05: c55.62,64.96 r1.25
  circle w0.05: c56.89,67.5 r1.25
  circle w0.05: c59.43,67.5 r1.25
  circle w0.05: c58.16,64.96 r1.25
  circle w0.05: c54.35,67.5 r1.25
  circle w0.05: c39.909,28.43 r1.25
  circle w0.05: c39.909,30.97 r1.25
  circle w0.05: c39.909,25.89 r1.25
